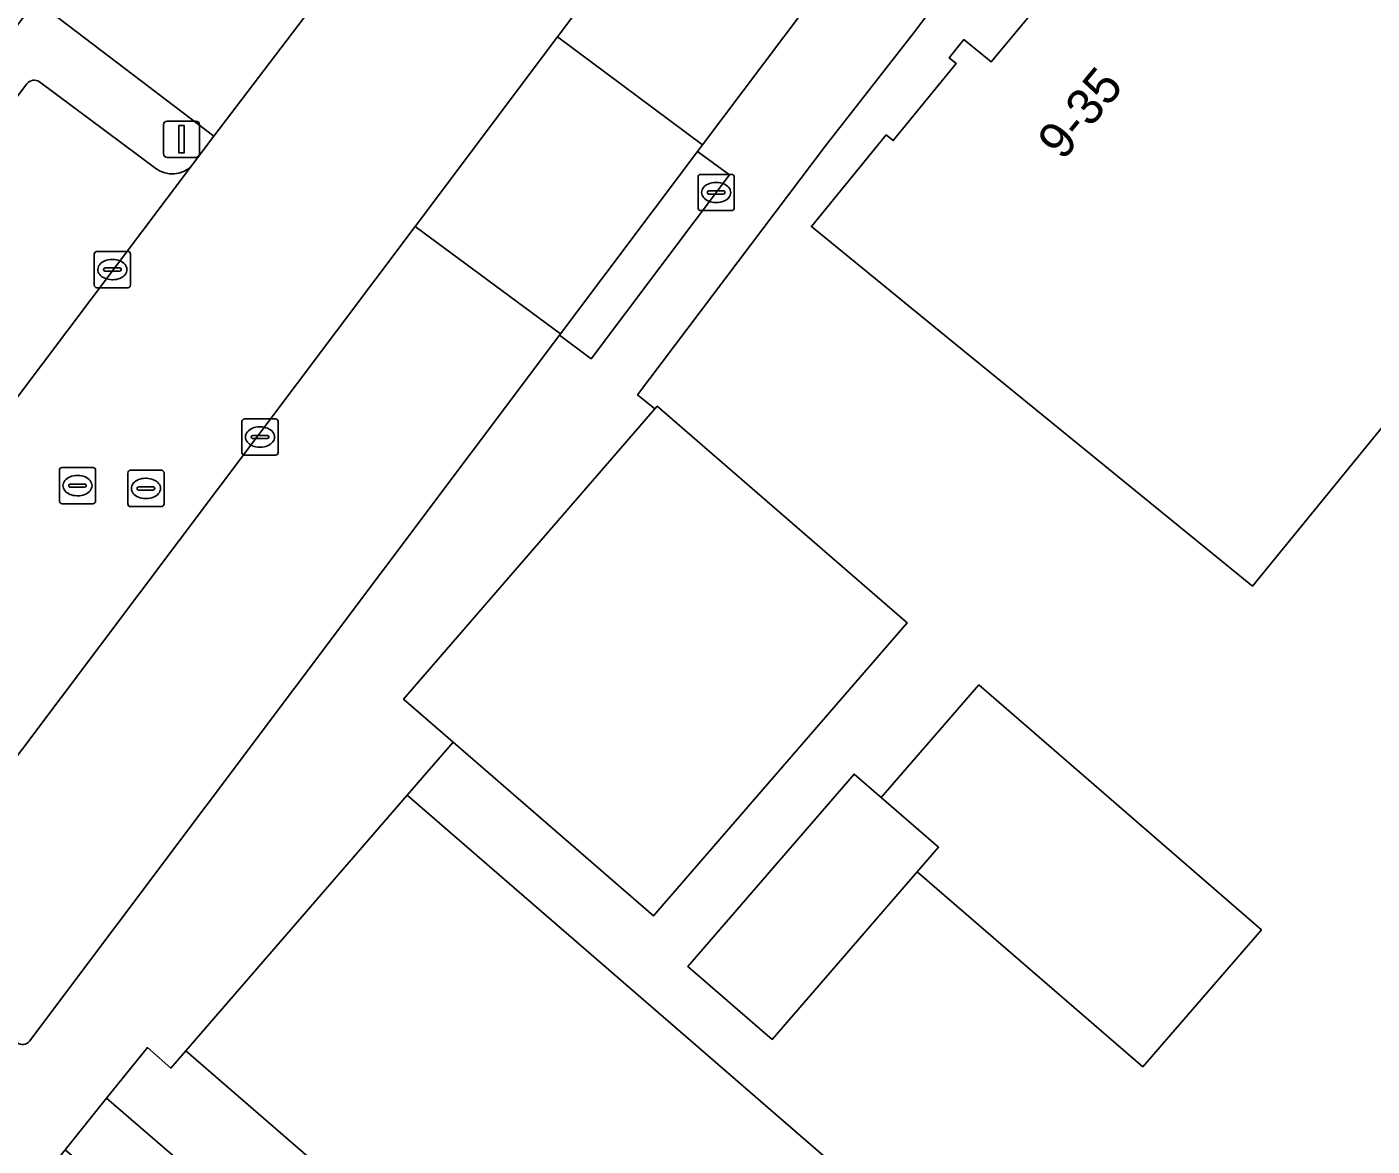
# Model space of a CAD drawing. Extents: x 161881 to 162523, y 381678 to 382381.
# Drawn here: x 161999.95 to 162037.06, y 382200.83 to 382231.71 of the extents above; entities that cross this region are included whole.
import ezdxf

# ---------------------------------------------------------------- set-up
doc = ezdxf.new("R2010")
doc.units = 0
for name, color, linetype in [('IMGEO_Brandkraan', 7, 'Continuous'), ('IMGEO_Erf', 7, 'Continuous'), ('IMGEO_Groenvoorziening', 7, 'Continuous'), ('IMGEO_Kolk', 7, 'Continuous'), ('IMGEO_Lichtmast', 7, 'Continuous'), ('IMGEO_Pand', 7, 'Continuous'), ('IMGEO_Pand_nummerreeks', 7, 'Continuous'), ('IMGEO_Parkeervlak_open', 7, 'Continuous'), ('IMGEO_Rijbaan_lokaal_open', 7, 'Continuous'), ('IMGEO_Rioolput', 7, 'Continuous'), ('IMGEO_Voetpad_open', 7, 'Continuous')]:
    doc.layers.add(name, color=color, linetype=linetype)

msp = doc.modelspace()

# ---------------------------------------------------------------- linework, layer by layer
at = {"layer": 'IMGEO_Brandkraan'}
for p, q in [((162018.466, 382226.715), (162018.466, 382227.567)), ((162018.541, 382227.641), (162019.393, 382227.641)), ((162018.954, 382227.421), (162018.979, 382227.421)), ((162019.467, 382227.567), (162019.467, 382226.715)), ((162018.725, 382227.135), (162018.725, 382227.147)), ((162019.163, 382227.098), (162018.765, 382227.098)), ((162018.768, 382227.184), (162019.166, 382227.184)), ((162019.209, 382227.147), (162019.209, 382227.135)), ((162019.393, 382226.641), (162018.541, 382226.641)), ((162018.977, 382226.861), (162018.952, 382226.861))]:
    msp.add_line(p, q, dxfattribs=at)
for points in [[(162018.466, 382226.715), (162018.466, 382227.567)], [(162018.541, 382227.641), (162019.393, 382227.641)], [(162019.467, 382227.567), (162019.467, 382226.715)], [(162019.393, 382226.641), (162018.541, 382226.641)]]:
    msp.add_lwpolyline(points, dxfattribs=at)
for centre, radius, start, end in [((162018.543, 382227.565), 0.0765, 91.552, 178.448), ((162018.543, 382227.565), 0.0765, 91.552, 178.448), ((162019.391, 382227.565), 0.0765, 1.552, 88.448), ((162019.391, 382227.565), 0.0765, 1.552, 88.448), ((162018.765, 382227.144), 0.0403, 85.8775, 175.7526), ((162018.762, 382227.134), 0.0366, 178.938, 274.7102), ((162019.166, 382227.141), 0.043, 264.8664, 352.4533), ((162019.17, 382227.146), 0.0386, 1.7309, 96.639), ((162018.543, 382226.717), 0.0765, 181.552, 268.448), ((162018.543, 382226.717), 0.0765, 181.552, 268.448), ((162019.391, 382226.717), 0.0765, 271.552, 358.448), ((162019.391, 382226.717), 0.0765, 271.552, 358.448)]:
    msp.add_arc(centre, radius, start, end, dxfattribs=at)
for centre, major_axis, ratio, start_param, end_param in [((162018.953, 382227.141), (-0.387, 0.002), 0.722429, 4.712389, 7.853982), ((162018.978, 382227.141), (-0.39, 0.002), 0.717154, 1.570796, 4.712389)]:
    msp.add_ellipse(centre, major_axis=major_axis, ratio=ratio, start_param=start_param, end_param=end_param, dxfattribs=at)
at = {"layer": 'IMGEO_Erf'}
for points in [[(162032.066, 382241.723), (162024.409, 382231.541), (162021.982, 382228.43), (162016.798, 382221.562), (162017.27, 382221.17), (162017.341, 382221.25), (162024.234, 382215.271), (162017.234, 382207.181), (162011.707, 382211.975), (162010.443, 382210.514), (162014.282, 382207.186), (162018.121, 382203.859), (162041.023, 382184.008)], [(162040.524, 382224.57), (162033.762, 382216.278), (162025.47, 382223.04), (162021.595, 382226.2), (162023.659, 382228.731), (162023.852, 382228.572), (162025.591, 382230.7), (162025.396, 382230.856), (162025.578, 382231.083), (162025.799, 382231.359), (162026.551, 382230.746), (162028.26, 382232.806)], [(162041.152, 382183.891), (162035.04, 382176.852), (162004.335, 382203.455), (162003.926, 382202.983), (162003.275, 382203.547), (162002.15, 382202.152), (162007.715, 382197.353), (162034.901, 382173.742), (162058.69, 382153.142)]]:
    msp.add_lwpolyline(points, dxfattribs=at)
msp.add_lwpolyline([(162030.737, 382203.02), (162024.516, 382208.4), (162020.512, 382203.771), (162018.182, 382205.787), (162022.773, 382211.095), (162023.519, 382210.448), (162026.213, 382213.555), (162034.009, 382206.793)], close=True, dxfattribs=at)
at = {"layer": 'IMGEO_Groenvoorziening'}
for points in [[(162004.494, 382227.876), (162005.109, 382228.696), (162000.199, 382232.429)], [(161986.711, 382212.523), (161999.951, 382230.14)], [(162000.298, 382230.196), (162003.509, 382227.805)]]:
    msp.add_lwpolyline(points, dxfattribs=at)
for centre, radius, start, end in [((162000.154, 382229.984), 0.257, 55.9195, 142.4156), ((162003.961, 382228.396), 0.744, 232.5642, 315.6814)]:
    msp.add_arc(centre, radius, start, end, dxfattribs=at)
at = {"layer": 'IMGEO_Kolk'}
for p, q in [((162001.809, 382224.589), (162001.809, 382225.441)), ((162001.884, 382225.515), (162002.736, 382225.515)), ((162002.81, 382225.441), (162002.81, 382224.589)), ((162002.111, 382225.058), (162002.509, 382225.058)), ((162002.297, 382225.295), (162002.322, 382225.295)), ((162002.068, 382225.009), (162002.068, 382225.021)), ((162002.506, 382224.972), (162002.108, 382224.972)), ((162002.32, 382224.735), (162002.295, 382224.735)), ((162002.552, 382225.021), (162002.552, 382225.009)), ((162002.736, 382224.515), (162001.884, 382224.515)), ((162005.882, 382219.968), (162005.882, 382220.82)), ((162005.957, 382220.894), (162006.809, 382220.894)), ((162006.37, 382220.674), (162006.395, 382220.674)), ((162006.883, 382220.82), (162006.883, 382219.968)), ((162006.141, 382220.388), (162006.141, 382220.4)), ((162006.579, 382220.351), (162006.181, 382220.351)), ((162006.184, 382220.437), (162006.582, 382220.437)), ((162006.625, 382220.4), (162006.625, 382220.388)), ((162006.809, 382219.894), (162005.957, 382219.894)), ((162006.393, 382220.114), (162006.368, 382220.114))]:
    msp.add_line(p, q, dxfattribs=at)
for points in [[(162001.809, 382224.589), (162001.809, 382225.441)], [(162001.884, 382225.515), (162002.736, 382225.515)], [(162002.81, 382225.441), (162002.81, 382224.589)], [(162002.736, 382224.515), (162001.884, 382224.515)], [(162005.882, 382219.968), (162005.882, 382220.82)], [(162005.957, 382220.894), (162006.809, 382220.894)], [(162006.883, 382220.82), (162006.883, 382219.968)], [(162006.809, 382219.894), (162005.957, 382219.894)]]:
    msp.add_lwpolyline(points, dxfattribs=at)
for centre, radius, start, end in [((162001.886, 382225.439), 0.0765, 91.552, 178.448), ((162001.886, 382225.439), 0.0765, 91.552, 178.448), ((162002.734, 382225.439), 0.0765, 1.552, 88.448), ((162002.734, 382225.439), 0.0765, 1.552, 88.448), ((162002.108, 382225.018), 0.0403, 85.8775, 175.7526), ((162002.513, 382225.02), 0.0386, 1.7309, 96.639), ((162002.105, 382225.008), 0.0366, 178.938, 274.7102), ((162002.509, 382225.015), 0.043, 264.8664, 352.4533), ((162001.886, 382224.591), 0.0765, 181.552, 268.448), ((162001.886, 382224.591), 0.0765, 181.552, 268.448), ((162002.734, 382224.591), 0.0765, 271.552, 358.448), ((162002.734, 382224.591), 0.0765, 271.552, 358.448), ((162005.959, 382220.818), 0.0765, 91.552, 178.448), ((162005.959, 382220.818), 0.0765, 91.552, 178.448), ((162006.807, 382220.818), 0.0765, 1.552, 88.448), ((162006.807, 382220.818), 0.0765, 1.552, 88.448), ((162006.181, 382220.397), 0.0403, 85.8775, 175.7526), ((162006.178, 382220.387), 0.0366, 178.938, 274.7102), ((162006.582, 382220.394), 0.043, 264.8664, 352.4533), ((162006.586, 382220.399), 0.0386, 1.7309, 96.639), ((162005.959, 382219.97), 0.0765, 181.552, 268.448), ((162005.959, 382219.97), 0.0765, 181.552, 268.448), ((162006.807, 382219.97), 0.0765, 271.552, 358.448), ((162006.807, 382219.97), 0.0765, 271.552, 358.448)]:
    msp.add_arc(centre, radius, start, end, dxfattribs=at)
for centre, major_axis, ratio, start_param, end_param in [((162002.296, 382225.015), (-0.387, 0.002), 0.722429, 4.712389, 7.853982), ((162002.321, 382225.015), (-0.39, 0.002), 0.717154, 1.570796, 4.712389), ((162006.369, 382220.394), (-0.387, 0.002), 0.722429, 4.712389, 7.853982), ((162006.394, 382220.394), (-0.39, 0.002), 0.717154, 1.570796, 4.712389)]:
    msp.add_ellipse(centre, major_axis=major_axis, ratio=ratio, start_param=start_param, end_param=end_param, dxfattribs=at)
at = {"layer": 'IMGEO_Lichtmast'}
for p, q in [((162003.722, 382228.211), (162003.722, 382229.011)), ((162003.722, 382229.011), (162003.722, 382228.211)), ((162003.822, 382229.111), (162004.612, 382229.111)), ((162004.612, 382229.111), (162003.822, 382229.111)), ((162004.712, 382229.011), (162004.712, 382228.211)), ((162004.712, 382228.211), (162004.712, 382229.011)), ((162004.612, 382228.111), (162003.822, 382228.111)), ((162003.822, 382228.111), (162004.612, 382228.111))]:
    msp.add_line(p, q, dxfattribs=at)
msp.add_lwpolyline([(162004.142, 382228.986), (162004.292, 382228.986), (162004.292, 382228.236), (162004.142, 382228.236), (162004.142, 382228.986)], dxfattribs=at)
for centre, start, end in [((162003.822, 382229.011), 90, 180), ((162003.822, 382229.011), 90, 180), ((162004.612, 382229.011), 0, 90), ((162004.612, 382229.011), 360, 90), ((162003.822, 382228.211), 180, 270), ((162003.822, 382228.211), 180, 270), ((162004.612, 382228.211), 270, 0), ((162004.612, 382228.211), 270, 0)]:
    msp.add_arc(centre, 0.1, start, end, dxfattribs=at)
at = {"layer": 'IMGEO_Pand'}
msp.add_lwpolyline([(162037.383, 382241.049), (162035.673, 382241.016), (162034.586, 382239.676), (162034.44, 382239.794), (162033.432, 382240.608), (162029.455, 382235.782), (162027.511, 382233.423), (162028.26, 382232.806), (162026.551, 382230.746), (162025.799, 382231.359), (162025.578, 382231.083), (162025.396, 382230.856), (162025.591, 382230.7), (162023.852, 382228.572), (162023.659, 382228.731), (162021.595, 382226.2), (162025.47, 382223.04), (162033.762, 382216.278), (162040.524, 382224.57)], dxfattribs=at)
for points in [[(162024.234, 382215.271), (162017.341, 382221.25), (162017.27, 382221.17), (162010.341, 382213.16), (162011.707, 382211.975), (162017.234, 382207.181)], [(162026.213, 382213.555), (162023.519, 382210.448), (162025.101, 382209.076), (162024.516, 382208.4), (162030.737, 382203.02), (162034.009, 382206.793)], [(162024.516, 382208.4), (162025.101, 382209.076), (162023.519, 382210.448), (162022.773, 382211.095), (162018.182, 382205.787), (162020.512, 382203.771)], [(162018.121, 382203.859), (162014.282, 382207.186), (162010.443, 382210.514), (162004.335, 382203.455), (162035.04, 382176.852), (162041.152, 382183.891), (162041.023, 382184.008)]]:
    msp.add_lwpolyline(points, close=True, dxfattribs=at)
at = {"layer": 'IMGEO_Parkeervlak_open'}
for points in [[(162019.647, 382238.162), (162014.591, 382231.432), (162018.589, 382228.455), (162023.101, 382234.466)], [(161999.951, 382230.14), (161986.711, 382212.523)], [(162003.509, 382227.805), (162000.298, 382230.196)], [(161990.138, 382208.807), (162004.494, 382227.876)], [(162014.645, 382223.2), (162014.673, 382223.238), (162010.665, 382226.206), (161995.464, 382205.989), (161995.52, 382206.048)], [(162000.023, 382203.725), (162014.645, 382223.2)]]:
    msp.add_lwpolyline(points, dxfattribs=at)
for centre, radius, start, end in [((162000.154, 382229.984), 0.257, 55.9195, 142.4156), ((162003.961, 382228.396), 0.744, 232.5642, 315.6814), ((161999.83, 382203.883), 0.249, 231.1737, 320.605)]:
    msp.add_arc(centre, radius, start, end, dxfattribs=at)
at = {"layer": 'IMGEO_Rijbaan_lokaal_open'}
for points in [[(162015.142, 382241.884), (162011.971, 382237.712), (162009.881, 382235.025), (162008.661, 382233.367), (162005.109, 382228.696), (162004.494, 382227.876), (161990.138, 382208.807), (161989.433, 382207.86), (161986.641, 382204.132), (161985.267, 382202.264), (161981.419, 382197.142), (161975.935, 382189.861)], [(161981.166, 382186.879), (161987.249, 382195.014), (161987.268, 382195.039), (161988.169, 382196.277), (161992.153, 382201.593), (161995.048, 382205.452), (161995.464, 382205.989), (162010.665, 382226.206), (162014.591, 382231.432), (162019.647, 382238.162), (162020.575, 382239.149), (162021.178, 382239.811)]]:
    msp.add_lwpolyline(points, dxfattribs=at)
msp.add_lwpolyline([(162018.451, 382228.271), (162018.589, 382228.455), (162014.591, 382231.432), (162010.665, 382226.206), (162014.673, 382223.238)], close=True, dxfattribs=at)
at = {"layer": 'IMGEO_Rioolput'}
for p, q in [((162000.921, 382219.553), (162001.773, 382219.553)), ((162000.846, 382218.627), (162000.846, 382219.479)), ((162001.334, 382219.333), (162001.359, 382219.333)), ((162001.847, 382219.479), (162001.847, 382218.627)), ((162002.734, 382218.549), (162002.734, 382219.401)), ((162002.809, 382219.475), (162003.661, 382219.475)), ((162003.222, 382219.255), (162003.247, 382219.255)), ((162003.735, 382219.401), (162003.735, 382218.549)), ((162001.105, 382219.047), (162001.105, 382219.059)), ((162001.543, 382219.01), (162001.145, 382219.01)), ((162001.148, 382219.096), (162001.546, 382219.096)), ((162001.357, 382218.773), (162001.332, 382218.773)), ((162001.589, 382219.059), (162001.589, 382219.047)), ((162002.993, 382218.969), (162002.993, 382218.981)), ((162003.431, 382218.932), (162003.033, 382218.932)), ((162003.036, 382219.018), (162003.434, 382219.018)), ((162003.477, 382218.981), (162003.477, 382218.969)), ((162001.773, 382218.553), (162000.921, 382218.553)), ((162003.661, 382218.475), (162002.809, 382218.475)), ((162003.245, 382218.695), (162003.22, 382218.695))]:
    msp.add_line(p, q, dxfattribs=at)
for points in [[(162000.921, 382219.553), (162001.773, 382219.553)], [(162000.846, 382218.627), (162000.846, 382219.479)], [(162001.847, 382219.479), (162001.847, 382218.627)], [(162002.734, 382218.549), (162002.734, 382219.401)], [(162002.809, 382219.475), (162003.661, 382219.475)], [(162003.735, 382219.401), (162003.735, 382218.549)], [(162001.773, 382218.553), (162000.921, 382218.553)], [(162003.661, 382218.475), (162002.809, 382218.475)]]:
    msp.add_lwpolyline(points, dxfattribs=at)
for centre, radius, start, end in [((162000.923, 382219.477), 0.0765, 91.552, 178.448), ((162000.923, 382219.477), 0.0765, 91.552, 178.448), ((162001.771, 382219.477), 0.0765, 1.552, 88.448), ((162001.771, 382219.477), 0.0765, 1.552, 88.448), ((162002.811, 382219.399), 0.0765, 91.552, 178.448), ((162002.811, 382219.399), 0.0765, 91.552, 178.448), ((162003.659, 382219.399), 0.0765, 1.552, 88.448), ((162003.659, 382219.399), 0.0765, 1.552, 88.448), ((162001.145, 382219.056), 0.0403, 85.8775, 175.7526), ((162001.142, 382219.046), 0.0366, 178.938, 274.7102), ((162001.546, 382219.053), 0.043, 264.8664, 352.4533), ((162001.55, 382219.058), 0.0386, 1.7309, 96.639), ((162003.033, 382218.978), 0.0403, 85.8775, 175.7526), ((162003.03, 382218.968), 0.0366, 178.938, 274.7102), ((162003.434, 382218.975), 0.043, 264.8664, 352.4533), ((162003.438, 382218.98), 0.0386, 1.7309, 96.639), ((162000.923, 382218.629), 0.0765, 181.552, 268.448), ((162000.923, 382218.629), 0.0765, 181.552, 268.448), ((162001.771, 382218.629), 0.0765, 271.552, 358.448), ((162001.771, 382218.629), 0.0765, 271.552, 358.448), ((162002.811, 382218.551), 0.0765, 181.552, 268.448), ((162002.811, 382218.551), 0.0765, 181.552, 268.448), ((162003.659, 382218.551), 0.0765, 271.552, 358.448), ((162003.659, 382218.551), 0.0765, 271.552, 358.448)]:
    msp.add_arc(centre, radius, start, end, dxfattribs=at)
for centre, major_axis, ratio, start_param, end_param in [((162001.333, 382219.053), (-0.387, 0.002), 0.722429, 4.712389, 7.853982), ((162001.358, 382219.053), (-0.39, 0.002), 0.717154, 1.570796, 4.712389), ((162003.221, 382218.975), (-0.387, 0.002), 0.722429, 4.712389, 7.853982), ((162003.246, 382218.975), (-0.39, 0.002), 0.717154, 1.570796, 4.712389)]:
    msp.add_ellipse(centre, major_axis=major_axis, ratio=ratio, start_param=start_param, end_param=end_param, dxfattribs=at)
at = {"layer": 'IMGEO_Voetpad_open'}
for points in [[(162025.692, 382242.462), (162028.273, 382240.499), (162025.361, 382236.673), (162024.718, 382237.167), (162022.821, 382234.676), (162023.101, 382234.466), (162018.589, 382228.455), (162018.451, 382228.271), (162019.33, 382227.626), (162015.518, 382222.556), (162014.645, 382223.2), (162000.023, 382203.725)], [(162002.15, 382202.152), (162003.275, 382203.547), (162003.926, 382202.983), (162004.335, 382203.455), (162010.443, 382210.514), (162011.707, 382211.975), (162010.341, 382213.16), (162017.27, 382221.17), (162016.798, 382221.562), (162021.982, 382228.43), (162024.409, 382231.541), (162032.066, 382241.723), (162033.432, 382240.608), (162034.44, 382239.794), (162036.342, 382242.085), (162037.377, 382242.139)], [(161971.158, 382194.01), (161972.599, 382195.923), (161981.714, 382207.935), (161985.77, 382204.806), (161988.573, 382208.526), (161984.491, 382211.627), (162000.199, 382232.429), (162005.109, 382228.696), (162008.661, 382233.367), (162007.53, 382234.195), (162005.076, 382236.059), (162002.356, 382238.121), (161998.699, 382233.61), (161986.724, 382217.648), (161983.018, 382212.725), (161980.809, 382209.736), (161980.257, 382208.989), (161970.32, 382195.912), (161960.433, 382193.097)], [(161979.998, 382181.502), (161980.177, 382180.625), (161988.587, 382187.894), (161990.016, 382186.254), (161991.197, 382187.619), (161990.744, 382188.005), (161993.971, 382192.007), (161997.877, 382196.852), (162001.003, 382200.728), (162002.15, 382202.152)], [(162058.69, 382153.142), (162034.901, 382173.742), (162007.715, 382197.353), (162002.15, 382202.152), (162001.003, 382200.728), (162001.87, 382200.001), (162006.547, 382195.968), (162007.937, 382194.769), (162008.089, 382194.637), (162014.192, 382189.336), (162015.213, 382188.449), (162026.877, 382178.317), (162027.903, 382177.426), (162030.56, 382175.118), (162039.593, 382167.298)]]:
    msp.add_lwpolyline(points, dxfattribs=at)
msp.add_lwpolyline([(162018.451, 382228.271), (162014.673, 382223.238), (162014.645, 382223.2), (162015.518, 382222.556), (162019.33, 382227.626)], close=True, dxfattribs=at)
msp.add_arc((161999.83, 382203.883), 0.249, 231.1737, 320.605, dxfattribs=at)

# ---------------------------------------------------------------- texts
at = {"layer": 'IMGEO_Pand_nummerreeks'}
msp.add_text('9-35', height=1, rotation=50.3205, dxfattribs=at).set_placement((162028.529, 382227.993))

doc.saveas('drawing.dxf')
